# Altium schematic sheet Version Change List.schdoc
size 649 x 194 mm
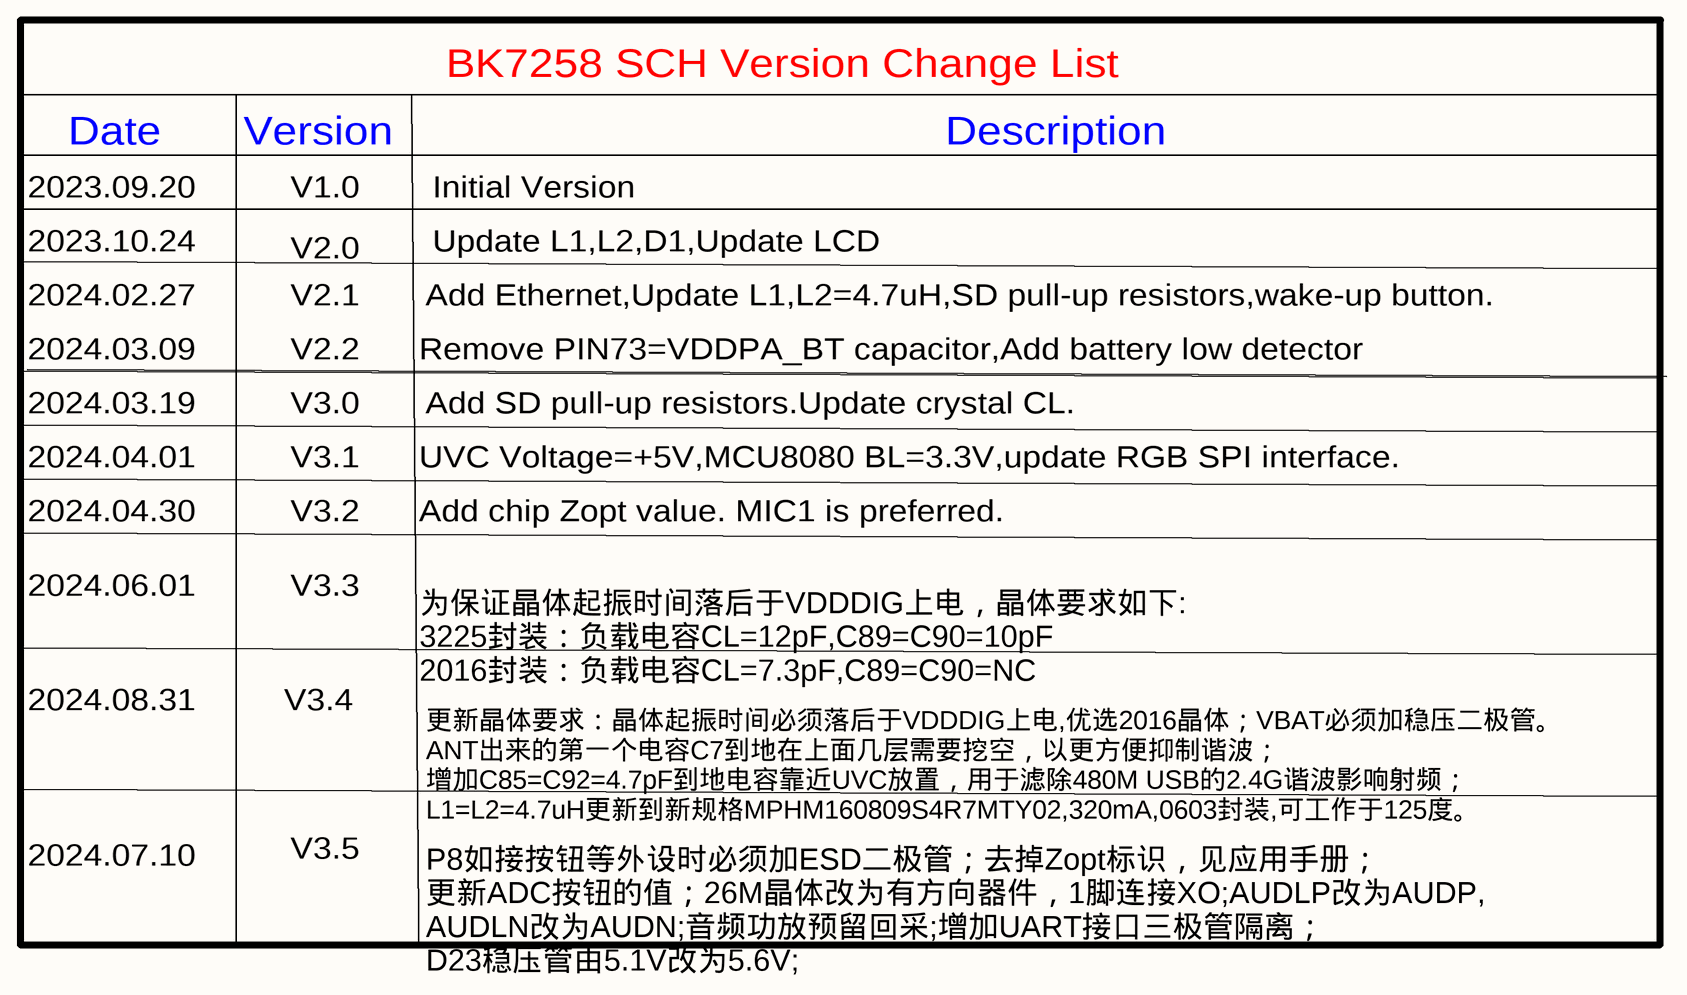
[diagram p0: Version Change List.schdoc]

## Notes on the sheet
- BK7258 SCH Version Change List
- Date
- Version
- Description
- 2023.09.20
- V1.0
- Initial Version
- 2023.10.24
- V2.0
- Update L1,L2,D1,Update LCD
- 2024.02.27
- V2.1
- Add Ethernet,Update L1,L2=4.7uH,SD pull-up resistors,wake-up button.
- 2024.03.09
- 2024.03.19
- V2.2
- V3.0
- Remove PIN73=VDDPA_BT capacitor,Add battery low detector
- Add SD pull-up resistors.Update crystal CL.
- 2024.04.01
- V3.1
- UVC Voltage=+5V,MCU8080 BL=3.3V,update RGB SPI interface.
- 2024.04.30
- V3.2
- Add chip Zopt value. MIC1 is preferred.
- 2024.06.01
- V3.3
- 为保证晶体起振时间落后于VDDDIG上电，晶体要求如下:
  3225封装：负载电容CL=12pF,C89=C90=10pF
  2016封装：负载电容CL=7.3pF,C89=C90=NC
- 2024.08.31
- V3.4
- 更新晶体要求：晶体起振时间必须落后于VDDDIG上电,优选2016晶体；VBAT必须加稳压二极管。
  ANT出来的第一个电容C7到地在上面几层需要挖空，以更方便抑制谐波；
  增加C85=C92=4.7pF到地电容靠近UVC放置，用于滤除480M USB的2.4G谐波影响射频；
  L1=L2=4.7uH更新到新规格MPHM160809S4R7MTY02,320mA,0603封装,可工作于125度。
- 2024.07.10
- V3.5
- P8如接按钮等外设时必须加ESD二极管；去掉Zopt标识，见应用手册；
  更新ADC按钮的值；26M晶体改为有方向器件，1脚连接XO;AUDLP改为AUDP,
  AUDLN改为AUDN;音频功放预留回采;增加UART接口三极管隔离；
  D23稳压管由5.1V改为5.6V;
